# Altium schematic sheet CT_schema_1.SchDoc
size 393 x 258 mm
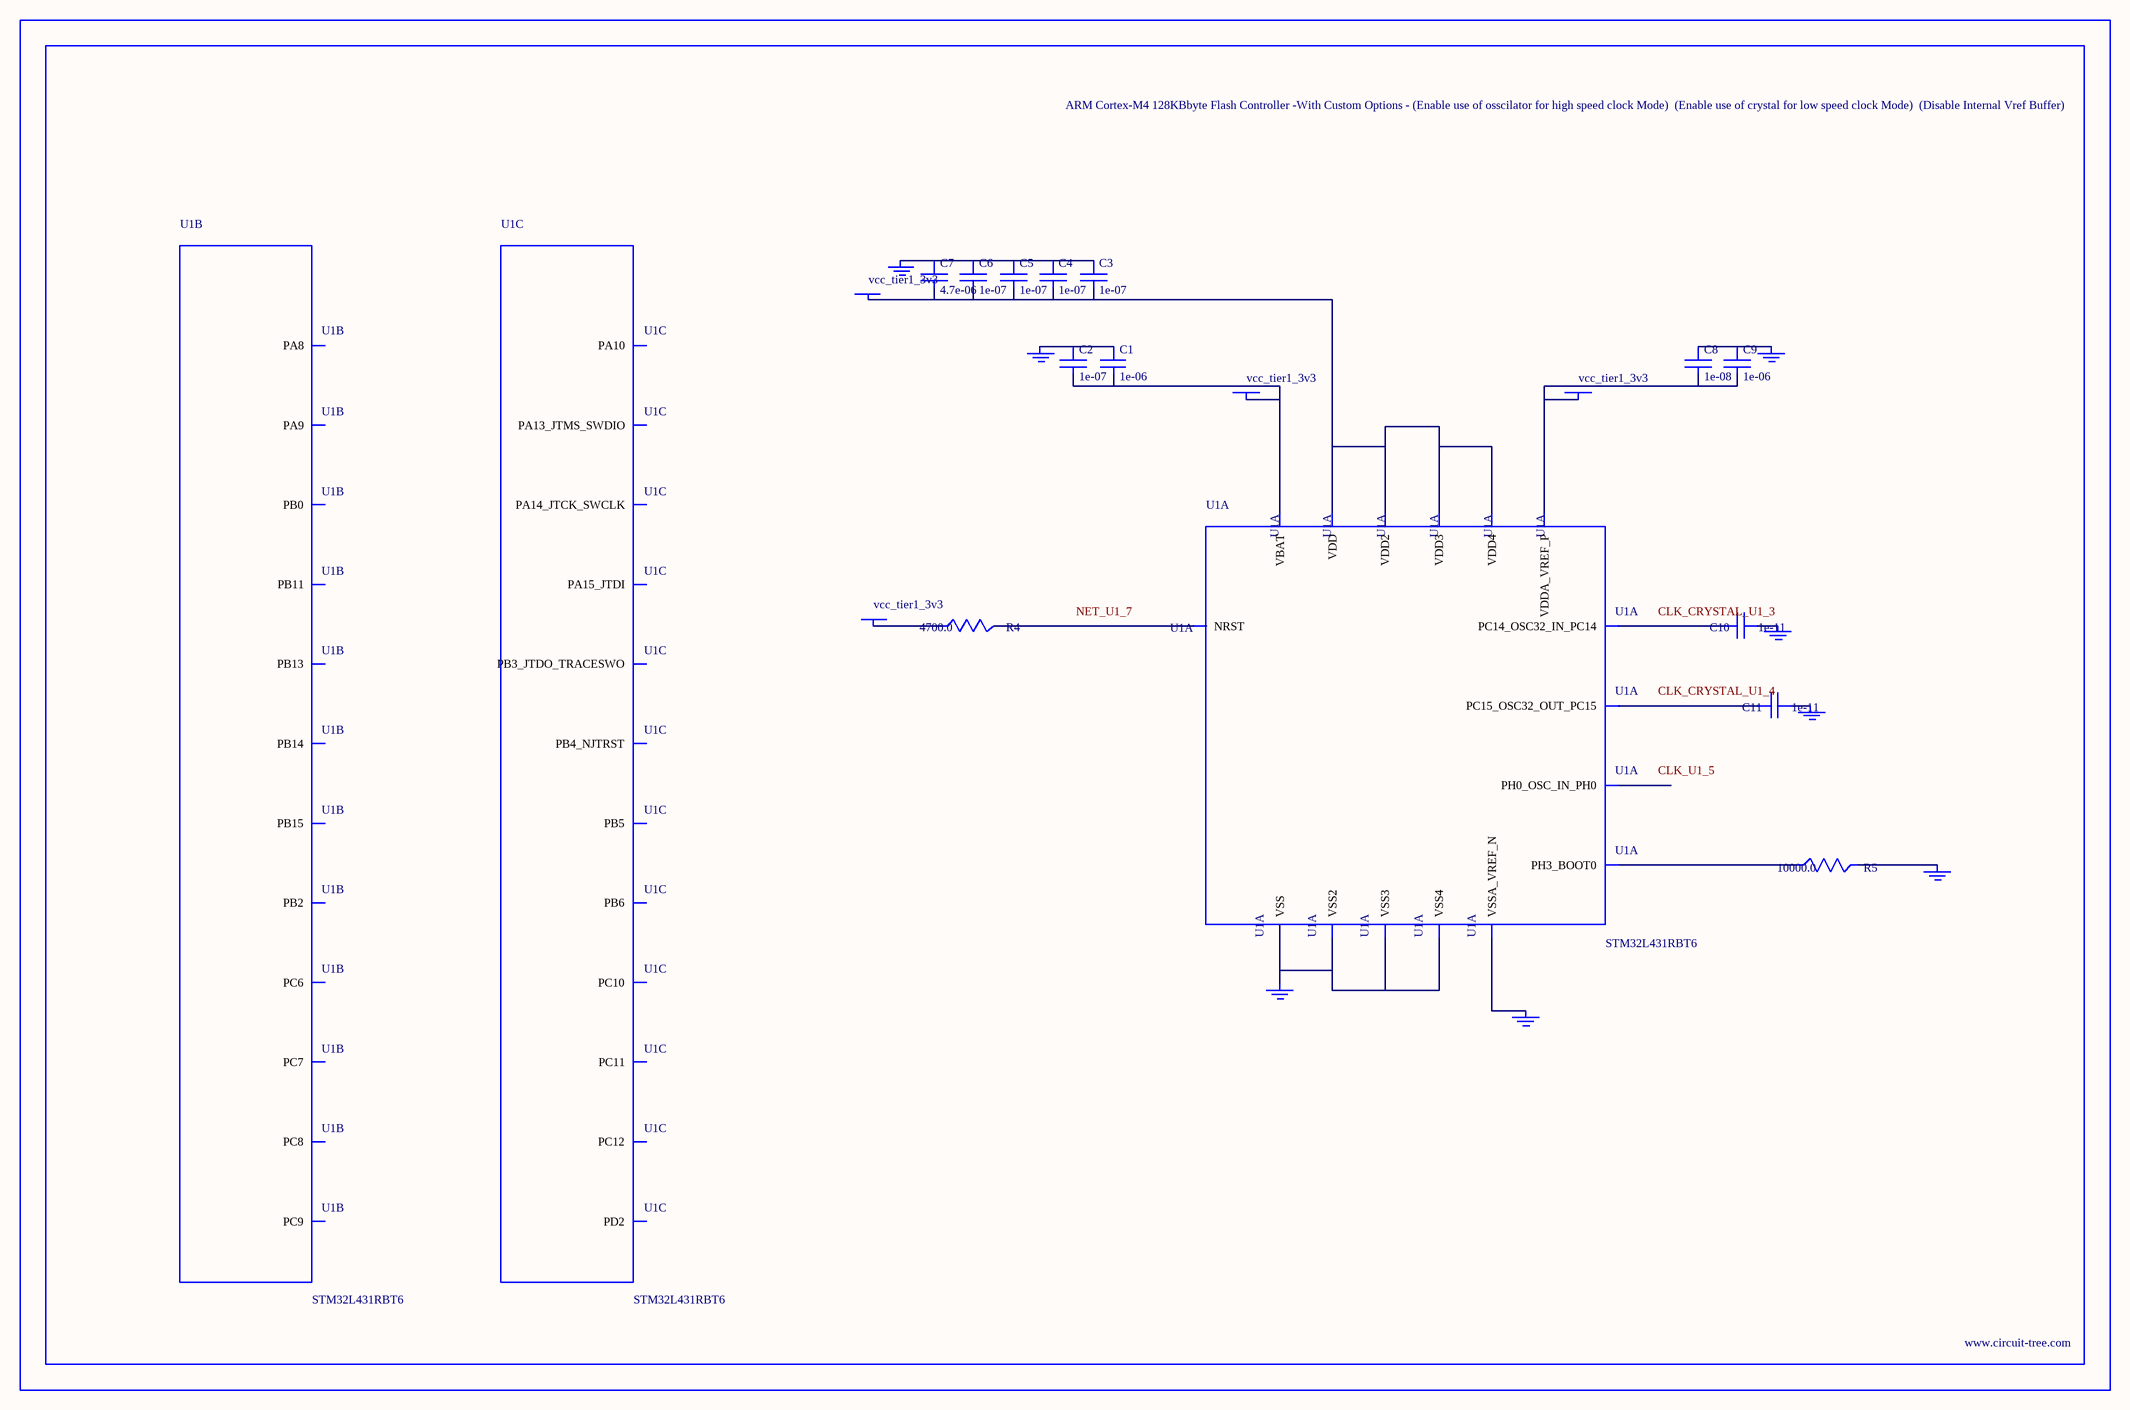
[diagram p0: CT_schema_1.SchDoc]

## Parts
BORDER0  (no value)
C1  1e-06  [C0603]
C2  1e-07  [C0603]
C3  1e-07  [C0603]
C4  1e-07  [C0603]
C5  1e-07  [C0603]
C6  1e-07  [C0603]
C7  4.7e-06  [C0603]
C8  1e-08  [C0603]
C9  1e-06  [C0603]
C10  1e-11  [C0402]
C11  1e-11  [C0402]
GND_INSTANCE_0_0  (no value)
GND_INSTANCE_0_1  (no value)
GND_INSTANCE_0_2  (no value)
GND_INSTANCE_0_3  (no value)
GND_INSTANCE_0_4  (no value)
GND_INSTANCE_0_5  (no value)
GND_INSTANCE_0_6  (no value)
GND_INSTANCE_0_7  (no value)
POWER_INSTANCE_0_0  vcc_tier1_3v3
POWER_INSTANCE_0_1  vcc_tier1_3v3
POWER_INSTANCE_0_2  vcc_tier1_3v3
POWER_INSTANCE_0_3  vcc_tier1_3v3
R4  4700.0  [R0603]
R5  10000.0  [R0603]
U1  STM32L431RBT6  [LQFP64]  (parts A,B,C of 7)

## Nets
NetC1_1: C1.1 C2.1 GND_INSTANCE_0_0.0(GND)
NetC1_2: C1.2 C2.2 POWER_INSTANCE_0_0.0(PWR) U1.1(VBAT)
NetC3_1: C3.1 C4.1 C5.1 C6.1 C7.1 GND_INSTANCE_0_5.0(GND)
NetC3_2: C3.2 C4.2 C5.2 C6.2 C7.2 POWER_INSTANCE_0_2.0(PWR) U1.19(VDD) U1.32(VDD2) U1.48(VDD3) U1.64(VDD4)
NetC8_1: C8.1 C9.1 GND_INSTANCE_0_4.0(GND)
NetC8_2: C8.2 C9.2 POWER_INSTANCE_0_1.0(PWR) U1.13(VDDA_VREF_P)
NetC10_1: C10.1 GND_INSTANCE_0_1.0(GND)
NetC10_2: C10.2 U1.3(PC14_OSC32_IN_PC14)
NetC11_1: C11.1 GND_INSTANCE_0_2.0(GND)
NetC11_2: C11.2 U1.4(PC15_OSC32_OUT_PC15)
NetGND_INSTANCE_0_3_0: GND_INSTANCE_0_3.0(GND) U1.12(VSSA_VREF_N)
NetGND_INSTANCE_0_6_0: GND_INSTANCE_0_6.0(GND) R5.2
NetGND_INSTANCE_0_7_0: GND_INSTANCE_0_7.0(GND) U1.18(VSS) U1.31(VSS2) U1.47(VSS3) U1.63(VSS4)
NetPOWER_INSTANCE_0_3_0: POWER_INSTANCE_0_3.0(PWR) R4.1
NetR4_2: R4.2 U1.7(NRST)
NetR5_1: R5.1 U1.60(PH3_BOOT0)

Not connected (* = marked no-connect by the designer): U1 5(PH0_OSC_IN_PH0) 26(PB0) 28(PB2) 30(PB11) 34(PB13) 35(PB14) 36(PB15) 37(PC6) 38(PC7) 39(PC8) 40(PC9) 41(PA8) 42(PA9) 43(PA10) 46(PA13_JTMS_SWDIO) 49(PA14_JTCK_SWCLK) 50(PA15_JTDI) 51(PC10) 52(PC11) 53(PC12) 54(PD2) 55(PB3_JTDO_TRACESWO) 56(PB4_NJTRST) 57(PB5) 58(PB6)

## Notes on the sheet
- Labels drawn without touching a wire or pin: CLK_CRYSTAL_U1_3, CLK_CRYSTAL_U1_4, CLK_U1_5, NET_U1_7

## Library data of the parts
BORDER0 = BORDER_PAGE0
C1 C9 = C0603C105K3RACTU
C2-C6 = 06035C104K4Z2A
C7 = GRM188R6YA475KE15D
C8 = 06035C103K4Z2A
C10 C11 = C0402C100K3GACTU
GND_INSTANCE_0_0-GND_INSTANCE_0_7 = GND
POWER_INSTANCE_0_0-POWER_INSTANCE_0_3 = PWR
R4 = RC0603JR-074K7L
R5 = RC0603JR-0710KL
